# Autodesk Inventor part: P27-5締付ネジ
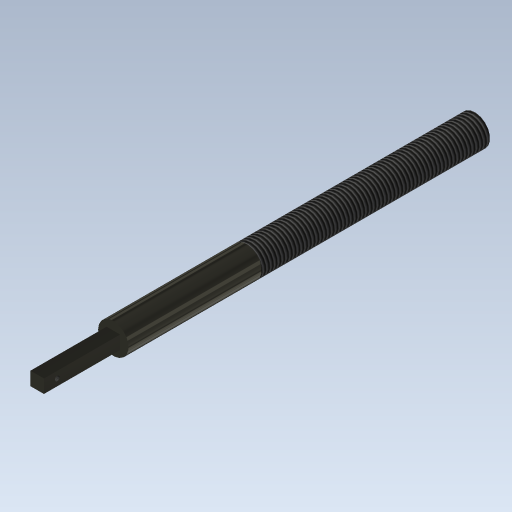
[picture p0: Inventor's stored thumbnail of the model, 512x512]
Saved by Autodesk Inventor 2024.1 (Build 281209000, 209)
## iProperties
Created: 2008-07
Part Number: P27-5締付ネジ
Document SubType Name: Modeling
Designer: y-shimohigashi
Density: 1 g/cm^3
Stock Number: P24-5締付ネジ
Material: 一般
Appearance: ガンメタル
Author: y-shimohigashi
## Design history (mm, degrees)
sketch "スケッチ2"
  geometry: C1 r 8 at (0, 0); 1 further point
  constraints: 1 centre point, 1 coincident
  dimensions: "d0" = 16 diameter of C1
extrude "押し出し1" new body sketch "スケッチ2" distance "d1" = 190; taper "d2" = 0 deg
sketch "スケッチ3"
  geometry: L1 (3.536, 3.536)-(-3.536, 3.536); L2 (-3.536, 3.536)-(-3.536, -3.536); L3 (-3.536, -3.536)-(3.536, -3.536); L4 (3.536, -3.536)-(3.536, 3.536); L5 (-3.536, 3.536)-(3.536, -3.536); 2 further points
  constraints: 10 end point, 2 parallel, 2 perpendicular, 1 coincident, 1 horizontal, 1 midpoint
  dimensions: "d3" = 10 distance of L1.end L3.end
extrude "押し出し2" join sketch "スケッチ3" distance "d4" = 40; taper "d5" = 0 deg
sketch "スケッチ4"
  geometry: L1 (-41.4, 0)-(-31.6, 0) reference; L2 (-40, -3.536)-(-40, 3.536) reference; 1 further point
  constraints: 1 point on line
  dimensions: "d6" = 7 distance from line of point (-33, 0) L2
hole "穴1" sketch "スケッチ4" diameter "d7" = 2.459; stored, may be unused: countersink angle "d11" = 90 deg, drill point angle "d13" = 118 deg; dims "d8" = 6, "d9" = 4, "d10" = 2, "d12" = 8
hole "穴2" sketch "スケッチ4" diameter "d14" = 2.459; stored, may be unused: countersink angle "d18" = 90 deg, drill point angle "d20" = 118 deg; dims "d15" = 6, "d16" = 4, "d17" = 2, "d19" = 8
feature "ねじ1" dims "d21" = 120, "d22" = 0
node "ソリッド1"
node "ソリッド ボディ"
node "サーフェス ボディ"
